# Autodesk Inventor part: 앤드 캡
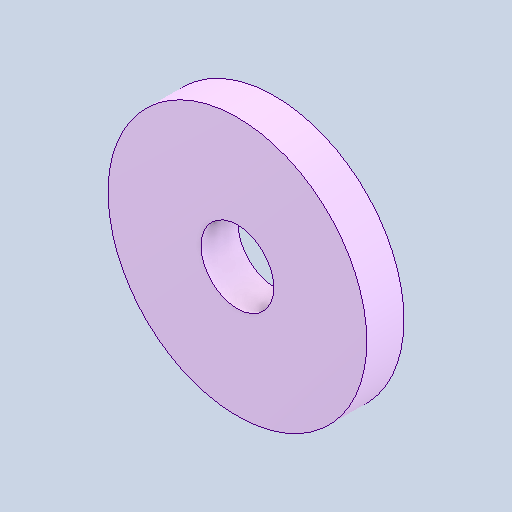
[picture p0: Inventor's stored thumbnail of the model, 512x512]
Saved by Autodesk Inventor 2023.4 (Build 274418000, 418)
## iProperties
Created: 2024-04
Part Number: 앤드 캡
Material: 강철, 연강
Document SubType Name: Modeling
Designer: EDU
Density: 7.86 g/cm^3
Appearance: 기본값
Author: jhkim
Sending System: Autodesk Inventor 2025
Preprocessor: ST-DEVELOPER v20
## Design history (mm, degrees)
node "앤드 캡1"
node "솔리드2"
node "솔리드1"
